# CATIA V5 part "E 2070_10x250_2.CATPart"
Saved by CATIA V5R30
Part number: E 2070_10x250_2
Definition: E 2070_10x250_1
Nomenclature: E 2070_10x250_1
Source: Unknown
Description: PART--DESC
Bounding box of the stored display mesh (mm): x 189.25 to 251.75, y -4.99 to 4.99, z 39.5 to 49.5
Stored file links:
  E:\Bakalarka\Model\Forma_v7\E 2070_10x250_2.CATPart
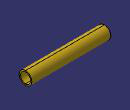
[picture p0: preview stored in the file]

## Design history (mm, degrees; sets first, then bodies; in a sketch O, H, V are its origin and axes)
Body1 "MANIFOLD_SOLID_BREP #156" (main body)
  Solid1: solid without history
  Pocket1: profile face of Solid1, direction along face of Solid1 reversed, length 187.5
